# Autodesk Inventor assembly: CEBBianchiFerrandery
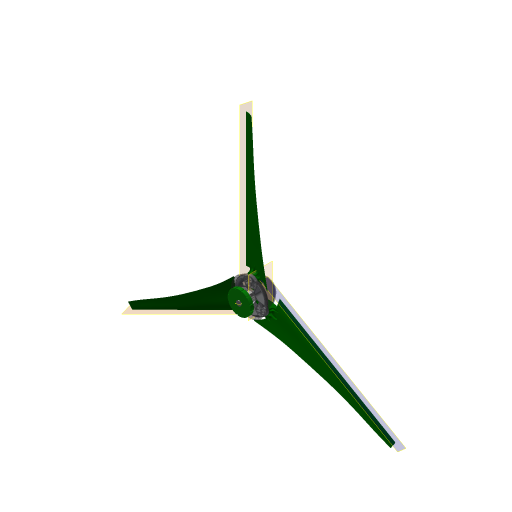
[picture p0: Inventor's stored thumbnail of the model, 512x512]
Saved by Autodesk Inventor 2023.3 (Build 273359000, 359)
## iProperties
Created: 2018-01
Part Number: CEBBianchiFerrandery
Document SubType Name: Assembly
Designer: formation
Author: formation
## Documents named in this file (7)
- C:\Travail\BTS TechCom\2-TechnoIndus\21-Meca\214-Systémes Industriels-SI\2141-Pièces Ecrites\21411-Cycle1\214112-TP02Eolienne\2141122-DossierTechniqueEolienne\21411223-Maquette numerique\214112233-CEC-Eolienne\CEC-Eoliene.iam
- C:\Travail\BTS TechCom\2-TechnoIndus\21-Meca\214-Systémes Industriels-SI\2141-Pièces Ecrites\21411-Cycle1\214112-TP02Eolienne\2141122-DossierTechniqueEolienne\21411223-Maquette numerique\214112233-CEC-Eolienne\07-Arbre rotor.ipt
- C:\Travail\BTS TechCom\2-TechnoIndus\21-Meca\214-Systémes Industriels-SI\2141-Pièces Ecrites\21411-Cycle1\214112-TP02Eolienne\2141122-DossierTechniqueEolienne\21411223-Maquette numerique\214112233-CEC-Eolienne\08-Rotor.ipt
- C:\Travail\BTS TechCom\2-TechnoIndus\21-Meca\214-Systémes Industriels-SI\2141-Pièces Ecrites\21411-Cycle1\214112-TP02Eolienne\2141122-DossierTechniqueEolienne\21411223-Maquette numerique\214112233-CEC-Eolienne\10-Entretoise.ipt
- C:\Travail\BTS TechCom\2-TechnoIndus\21-Meca\214-Systémes Industriels-SI\2141-Pièces Ecrites\21411-Cycle1\214112-TP02Eolienne\2141122-DossierTechniqueEolienne\21411223-Maquette numerique\214112233-CEC-Eolienne\09-BS 290 SKF - SKF 6203-RS1.ipt
- C:\Travail\BTS TechCom\2-TechnoIndus\21-Meca\214-Systémes Industriels-SI\2141-Pièces Ecrites\21411-Cycle1\214112-TP02Eolienne\2141122-DossierTechniqueEolienne\21411223-Maquette numerique\214112233-CEC-Eolienne\Helice\Hélice.iam
- C:\Users\Thier\OneDrive\Documents\Inventor\Content Center Files\R2023\fr-FR\ISO 4032(3)\ISO 4032 - M18NF EN.ipt
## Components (7 placed, 6 different names)
1. 07-Arbre rotor:1 — Angle:1, Logement:5
2. 08-Rotor:1 — Logement:1, Angle:1, Logement:5
3. 10-Entretoise:1 — Insert:3, Insert:4
4. BS 290 SKF- with RS1 seal SKF 6203-RS1:1 — Insert:3, Logement:1
5. BS 290 SKF- with RS1 seal SKF 6203-RS1:2 — Insert:4, Logement:6
6. Hélice:1 [sub-assembly] — Logement:6, Logement:7
7. NF EN 24032 M18:1 — Logement:7
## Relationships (7: Insert 6, Angle 1)
- Logement:1 [Insert]: 08-Rotor:1 ↔ BS 290 SKF- with RS1 seal SKF 6203-RS1:1
- Insert:3: 10-Entretoise:1 ↔ BS 290 SKF- with RS1 seal SKF 6203-RS1:1
- Insert:4: 10-Entretoise:1 ↔ BS 290 SKF- with RS1 seal SKF 6203-RS1:2
- Angle:1: 07-Arbre rotor:1 ↔ 08-Rotor:1
- Logement:5 [Insert]: 07-Arbre rotor:1 ↔ 08-Rotor:1
- Logement:6 [Insert]: BS 290 SKF- with RS1 seal SKF 6203-RS1:2 ↔ Hélice:1
- Logement:7 [Insert]: Hélice:1 ↔ NF EN 24032 M18:1
